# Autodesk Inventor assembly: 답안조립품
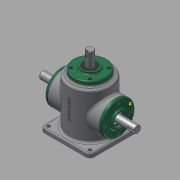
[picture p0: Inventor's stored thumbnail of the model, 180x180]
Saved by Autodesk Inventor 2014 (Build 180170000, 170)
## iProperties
Created: 2015-10
Part Number: 답안조립품
Document SubType Name: Assembly
Designer: USER
Author: USER
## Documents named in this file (14)
- C:\Users\USER\Desktop\451007V1015\답안조립품.iam
- C:\Users\USER\Desktop\451007V1015\본체.ipt
- C:\Users\USER\Desktop\451007V1015\베어링 6203.ipt
- C:\Users\USER\Desktop\451007V1015\커버.ipt
- C:\Users\USER\Desktop\451007V1015\서브 축.ipt
- 서브 축.ipt
- C:\Users\USER\Desktop\451007V1015\키 4x4.ipt
- C:\Users\USER\Desktop\451007V1015\M4.ipt
- C:\Users\USER\Desktop\451007V1015\오일실.ipt
- C:\Users\USER\Desktop\451007V1015\메인 축.ipt
- 메인 축.ipt
- C:\Users\USER\Desktop\451007V1015\키 5x5.ipt
- C:\Users\USER\Desktop\451007V1015\메인 베벨기어.ipt
- C:\Users\USER\Desktop\451007V1015\서브 베벨기어.ipt
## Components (12 placed, 1 different names)
1. M4:1
2. M4:2
3. M4:3
4. M4:4
5. M4:6
6. M4:7
7. M4:8
8. M4:9
9. M4:5
10. M4:10
11. M4:11
12. M4:12
## Named parameters: d16_d13 = 0, d17_d14 = 0, d18_d15 = 0, d19_d11 = 0
